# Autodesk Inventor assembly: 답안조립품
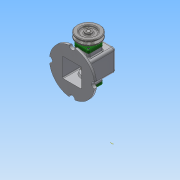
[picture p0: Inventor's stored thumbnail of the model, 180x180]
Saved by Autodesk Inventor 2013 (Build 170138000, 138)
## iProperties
Created: 2018-07
Part Number: 답안조립품
Document SubType Name: Assembly
Designer: Administrator
Author: Administrator
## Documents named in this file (16)
- C:\Users\Administrator\Desktop\480708V1005\답안조립품.iam
- C:\Users\Administrator\Desktop\480708V1005\부품1.ipt
- C:\Users\Administrator\Desktop\480708V1005\V벨트풀리.ipt
- C:\Users\Administrator\Desktop\480708V1005\고정핀 1.2x8.ipt
- C:\Users\Administrator\Desktop\480708V1005\뒤커버.ipt
- C:\Users\Administrator\Desktop\480708V1005\링크.ipt
- C:\Users\Administrator\Desktop\480708V1005\멈춤나사 M3x8.ipt
- C:\Users\Administrator\Desktop\480708V1005\베어링 12x32x10.ipt
- C:\Users\Administrator\Desktop\480708V1005\볼트 M4.ipt
- C:\Users\Administrator\Desktop\480708V1005\부시.ipt
- C:\Users\Administrator\Desktop\480708V1005\슬라이드.ipt
- C:\Users\Administrator\Desktop\480708V1005\앞커버.ipt
- C:\Users\Administrator\Desktop\480708V1005\오일 실 12 25 7.ipt
- C:\Users\Administrator\Desktop\480708V1005\키 4x4x10.ipt
- C:\Users\Administrator\Desktop\480708V1005\편심축.ipt
- C:\Users\Administrator\Desktop\480708V1005\핀 5x18.ipt
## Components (3 placed, 3 different names)
1. V벨트풀리:1
2. 고정핀 1.2x8:1
3. 핀 5x18:1
